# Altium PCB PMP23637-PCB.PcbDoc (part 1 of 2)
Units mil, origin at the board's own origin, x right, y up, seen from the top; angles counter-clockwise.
Board outline 3000 x 2000 mil, 6 copper layers (Top Layer, Layer 2, Signal Layer 3, Signal Layer 4, Layer 5, Bottom Layer), stack 61.712 mil thick; 143 components, 52 nets, 318 pads, 582 vias.
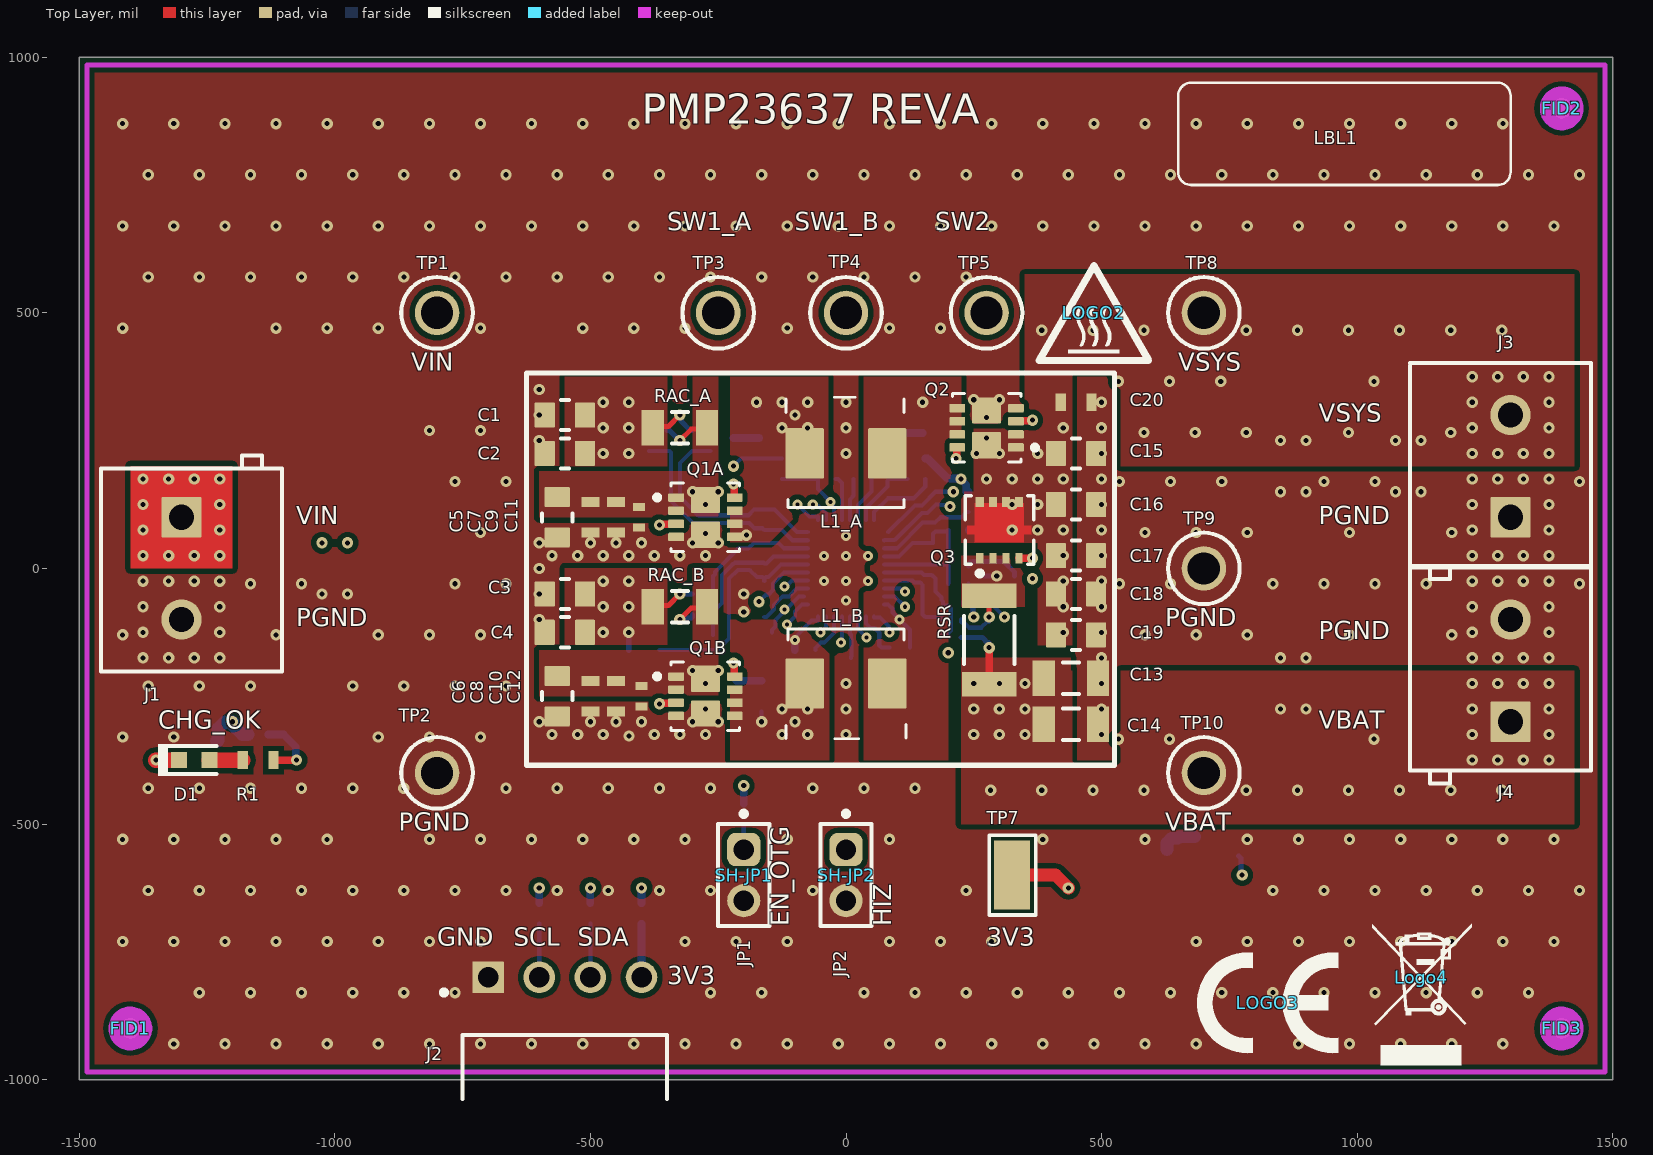
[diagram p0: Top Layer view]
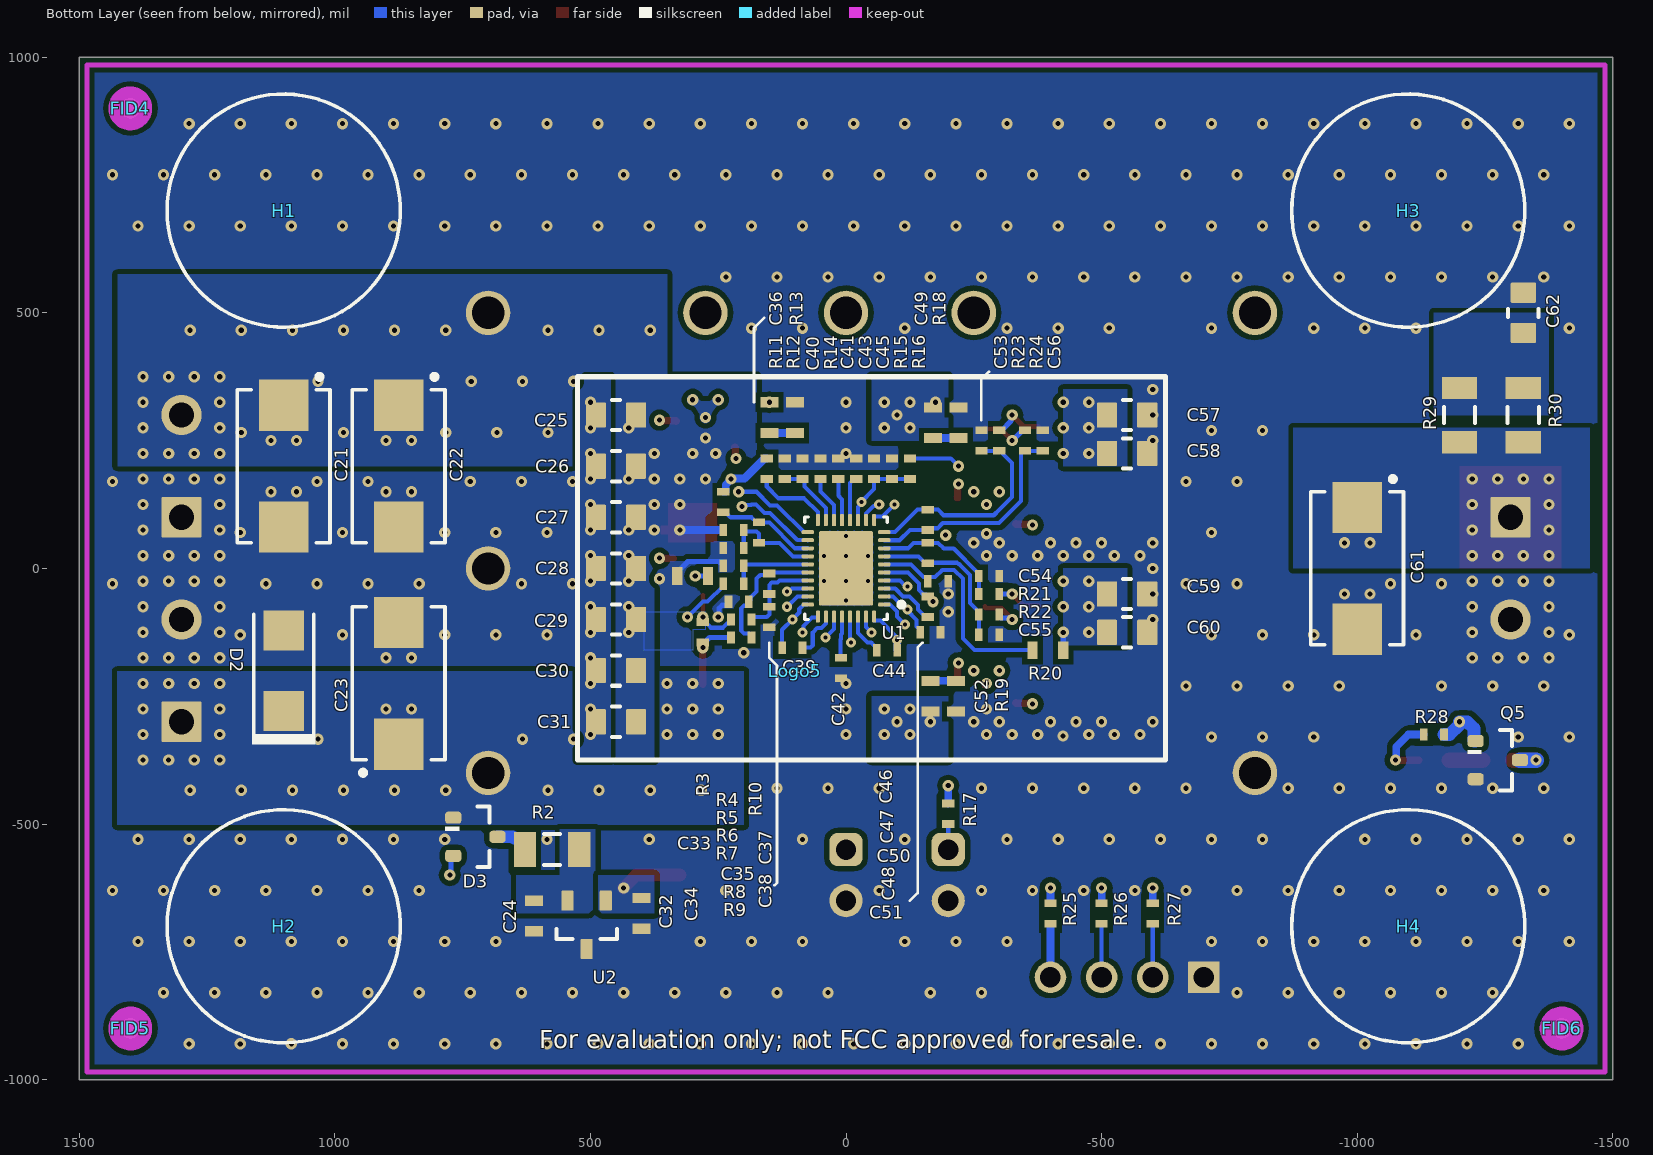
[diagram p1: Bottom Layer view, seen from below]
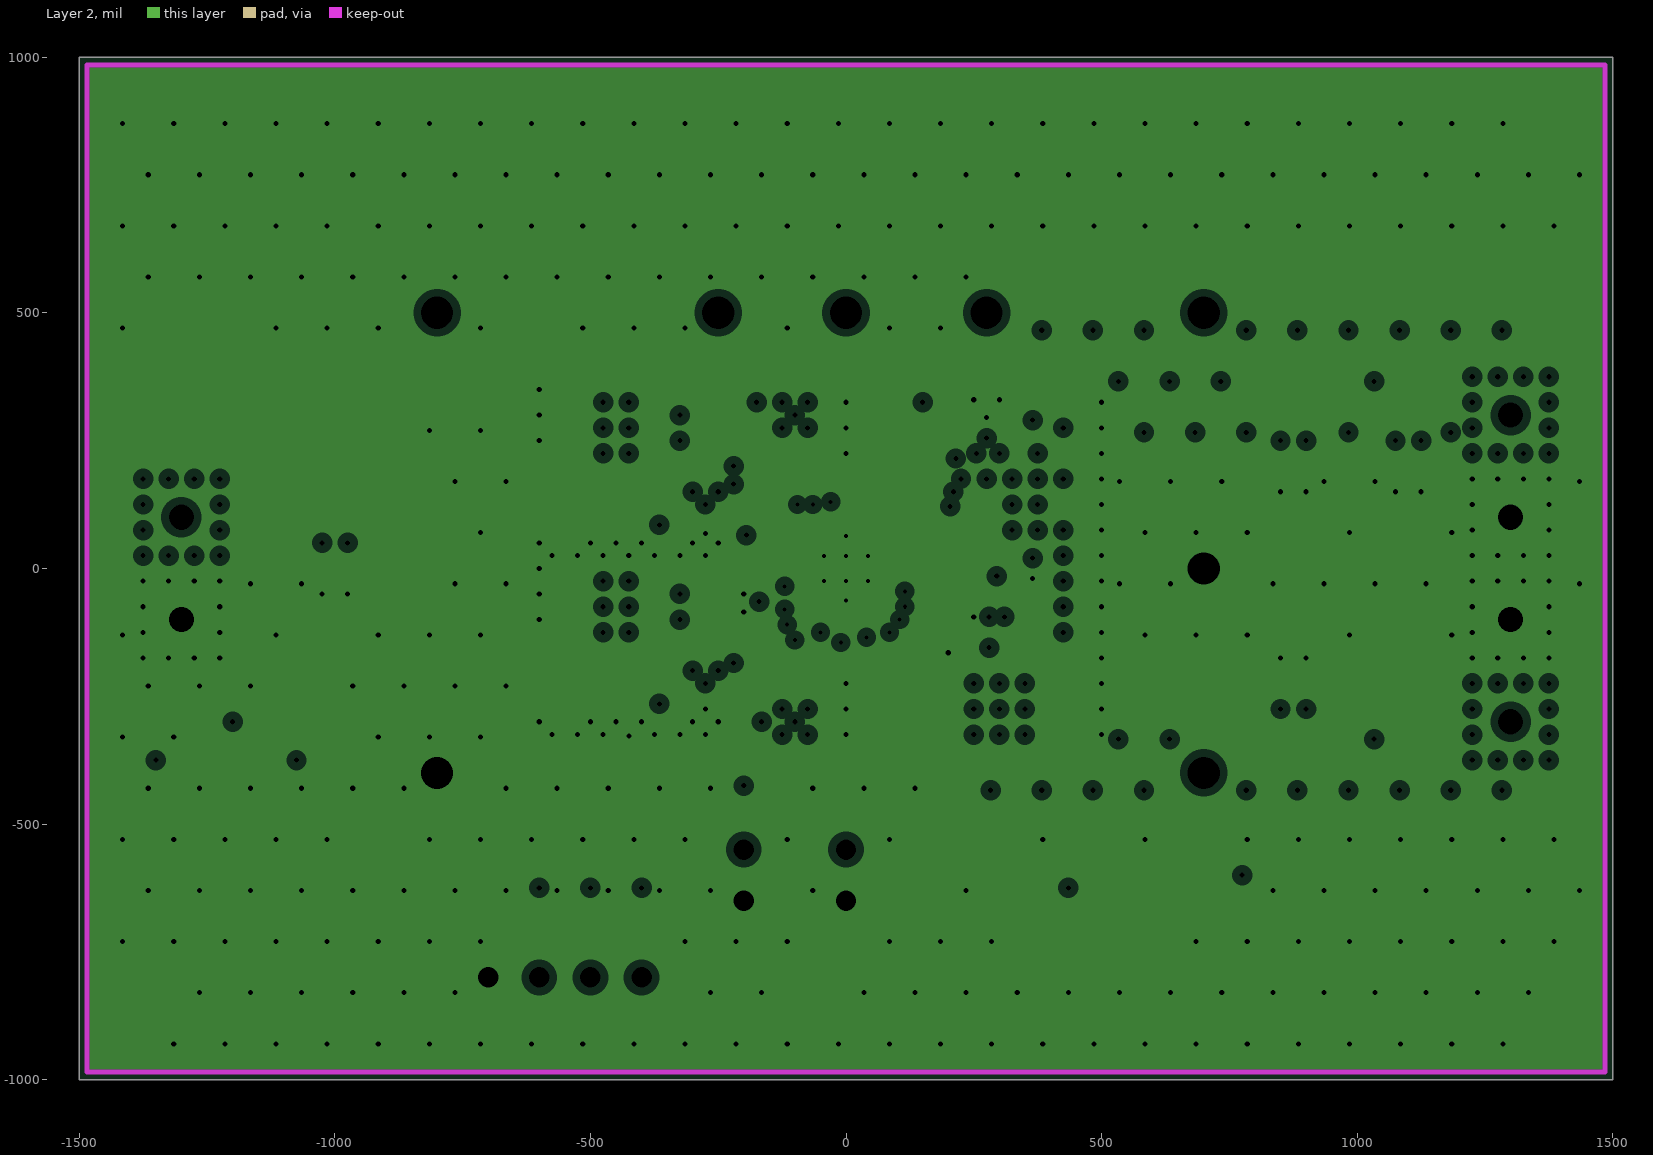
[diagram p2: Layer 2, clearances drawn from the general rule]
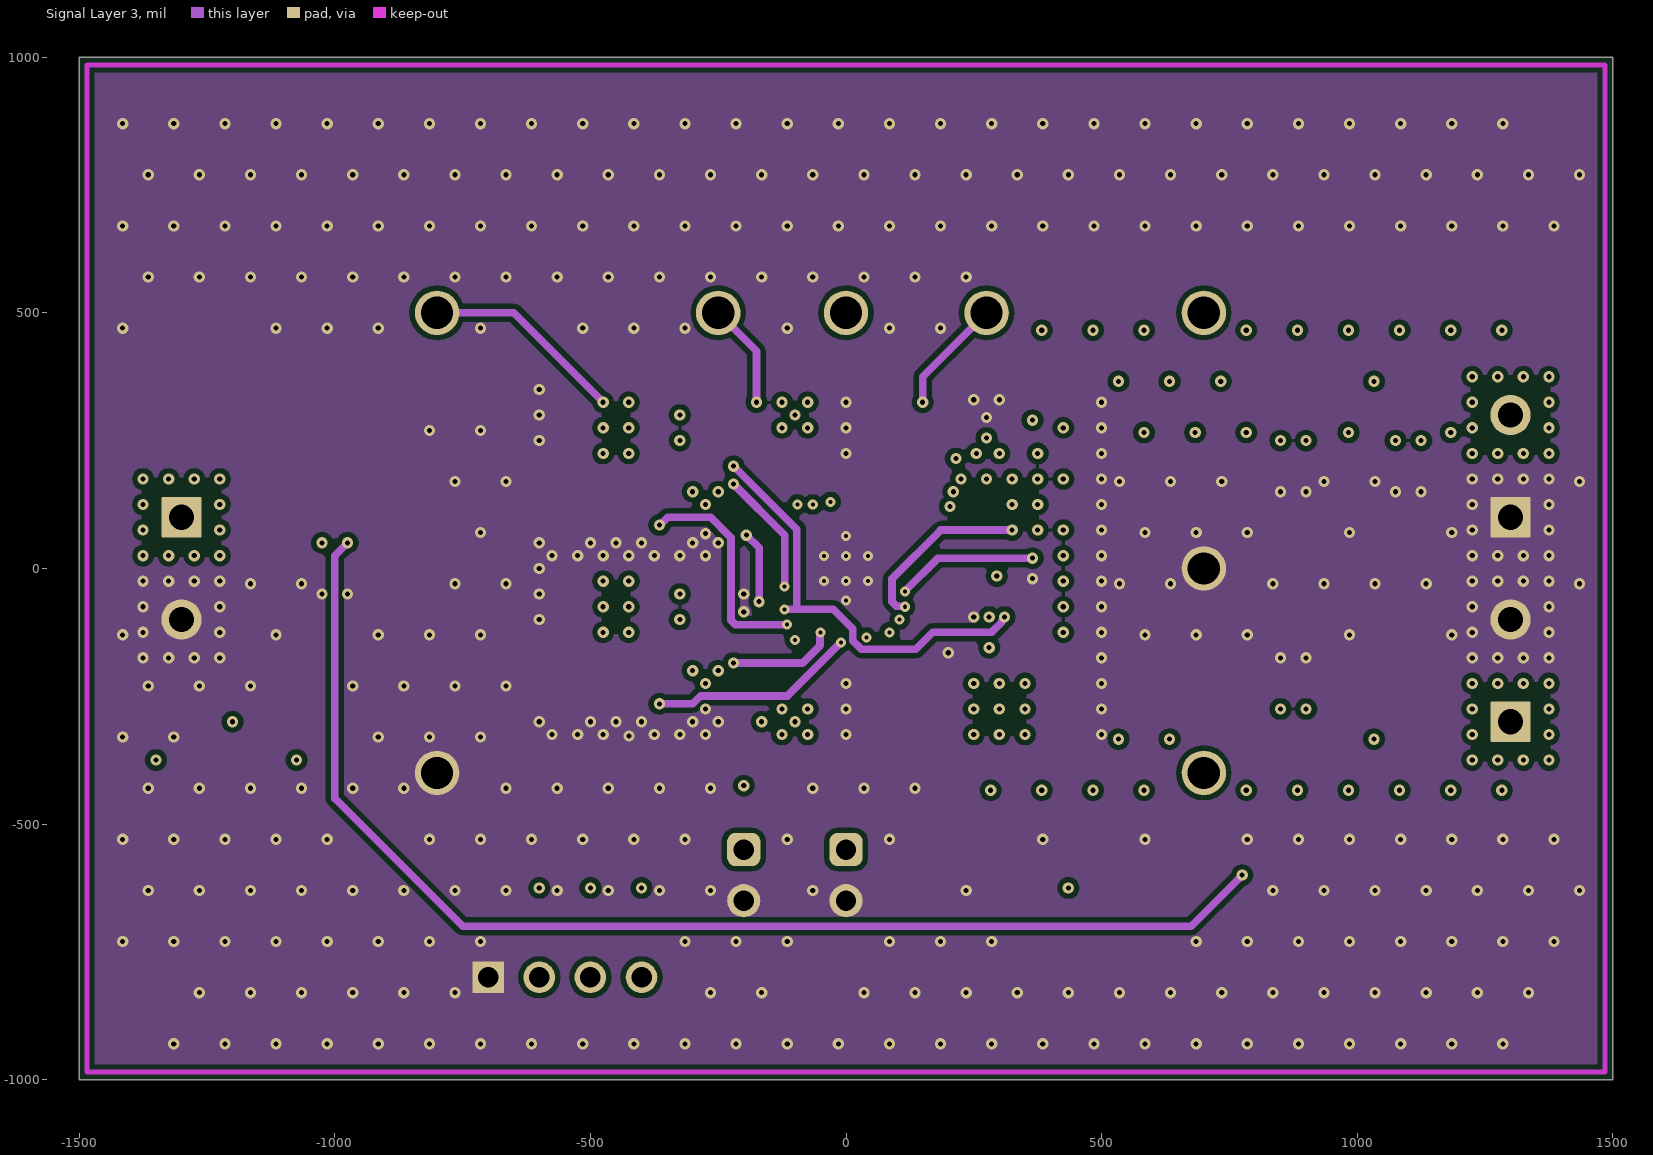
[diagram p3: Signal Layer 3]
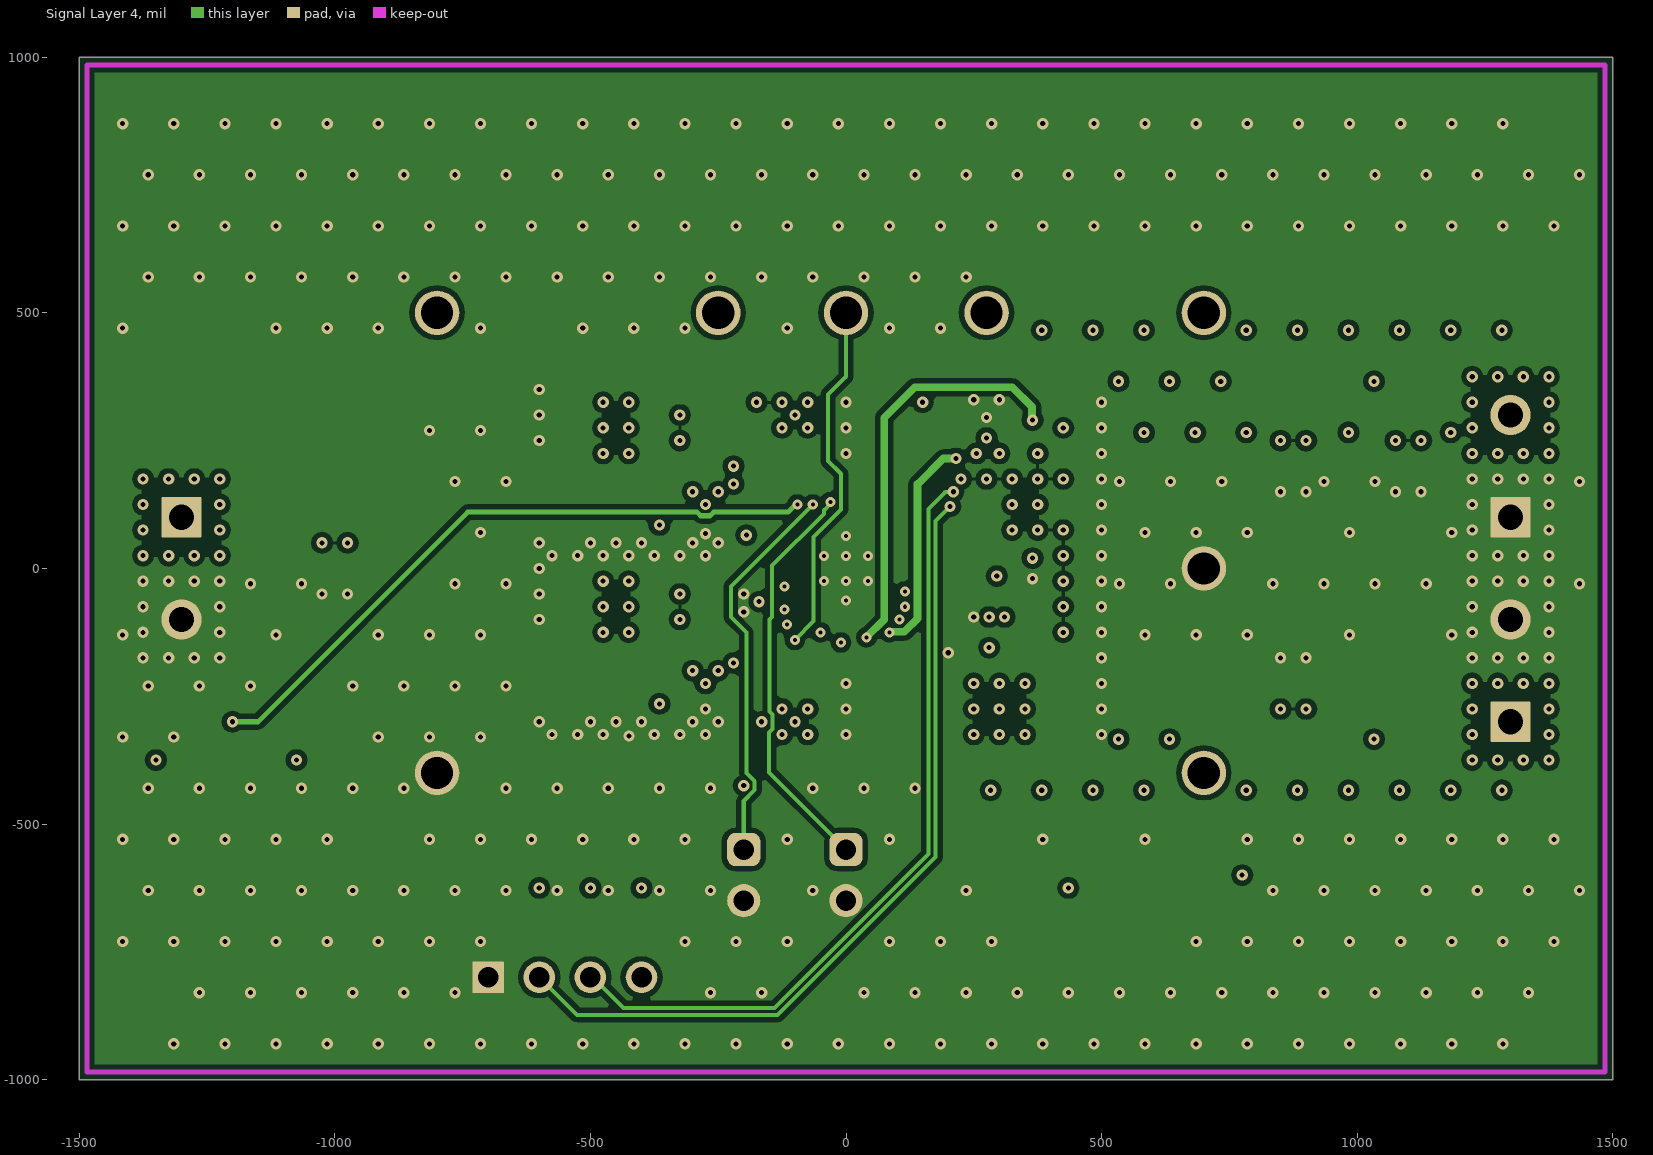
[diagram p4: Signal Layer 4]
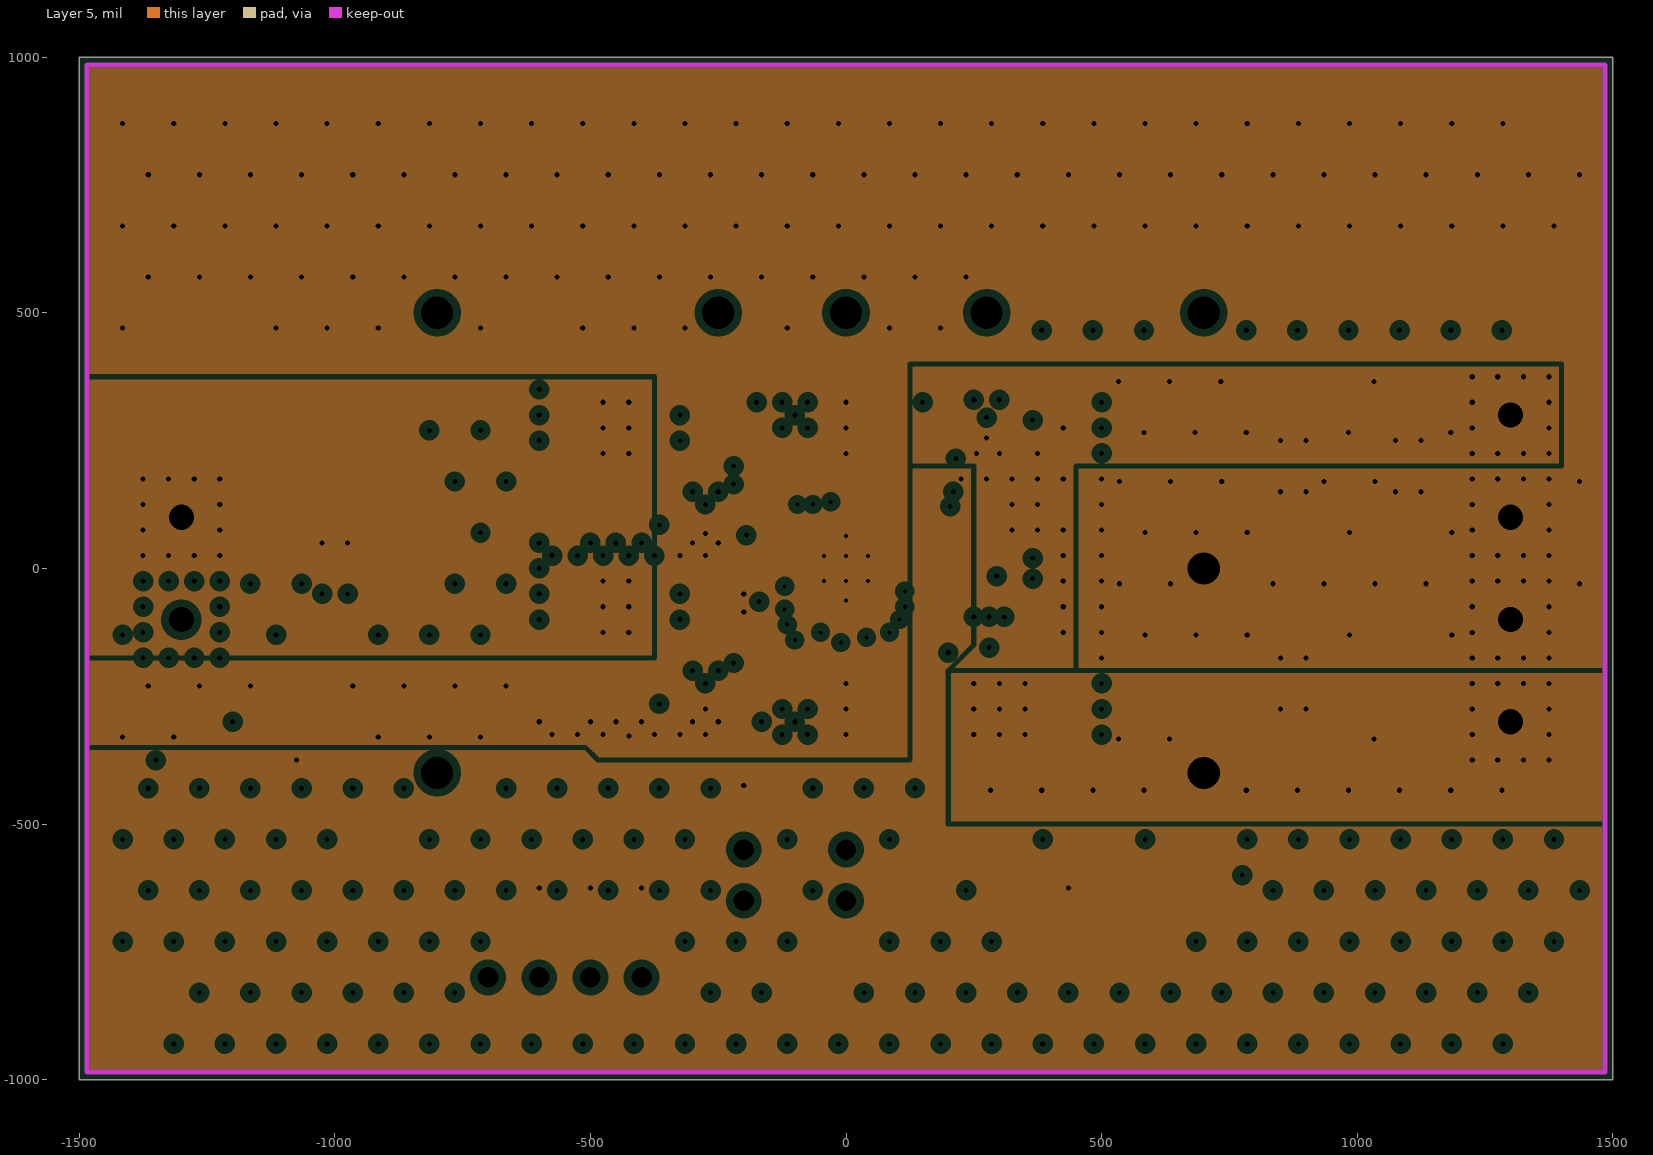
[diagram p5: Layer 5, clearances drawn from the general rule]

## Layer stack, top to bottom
Top Solder: solder mask 0.4, Solder Resist, Dk 3.5
Top Layer: signal copper 2.8
Dielectric1: core 5, FR-4 High TG, Dk 4.2
Layer 2: plane copper 2.756, net PGND
Dielectric 1: prepreg 5, PP-006, Dk 4.1
Signal Layer 3: signal copper 2.8
Dielectric 2: prepreg 25, FR-4 High TG, Dk 4.2
Signal Layer 4: signal copper 2.8
Dielectric 4: prepreg 5, PP-006, Dk 4.1
Layer 5: plane copper 2.756, net (Multiple Nets)
Dielectric 3: core 5, FR-4 High TG, Dk 4.2
Bottom Layer: signal copper 2.8
Bottom Solder: solder mask 0.4, Solder Resist, Dk 3.5

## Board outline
-1500,1000 -1500,-1000 1500,-1000 1500,1000

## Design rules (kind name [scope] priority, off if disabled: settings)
AcuteAngle [All] p1: minimum=4.50000000000000E+0001 checktracksonly=FALSE
AssemblyTestPointUsage [All] p1: valid=2
Clearance "Clearance_gnd polyd" [(InNet('GND') or InNet('PGND')) and inpoly] p1: gap=10 ignorepadtopadclearanceinfootprint=FALSE
Clearance Clearance_FETs [hasfootprint('TRANS_NexFET_Q3') or hasfootprint('TRANS_NexFET_Q3A')] p2: gap=5.9 ignorepadtopadclearanceinfootprint=FALSE except(0: Arc-Hole Track-Hole SMDPad-Hole THPad-Hole Via-Hole Fill-Hole Poly-Hole Region-Hole Text-Hole)
Clearance Clearance_Keepouts [((IsTrack Or IsArc) And Not InPoly) And IsFree and IsKeepOut vs ((IsTrack Or IsArc) And Not InPoly) And IsFree and IsKeepOut] p3: gap=25 ignorepadtopadclearanceinfootprint=FALSE
Clearance Clearance_BoardEdge_MountingHoles [OnCopper and InComponentClass('Mounting Holes') vs IsKeepOut] p4: gap=40 ignorepadtopadclearanceinfootprint=FALSE except(0: Arc-Hole Track-Hole SMDPad-Hole THPad-Hole Via-Hole Fill-Hole Poly-Hole Region-Hole Text-Hole)
Clearance Clearance_BoardEdge_Poly [OnCopper and InPoly vs IsKeepOut] p5: gap=25 ignorepadtopadclearanceinfootprint=FALSE except(0: Arc-Hole Track-Hole SMDPad-Hole THPad-Hole Via-Hole Fill-Hole Poly-Hole Region-Hole Text-Hole)
Clearance Clearance_BoardEdge [OnCopper and Not InComponentClass('Logo') and not InComponentClass('FiducialMark') and not InRegion(1000,500,4000,800) and Not IsKeepout vs IsKeepOut] p6: gap=25 ignorepadtopadclearanceinfootprint=FALSE except(0: Arc-Hole Track-Hole SMDPad-Hole THPad-Hole Via-Hole Fill-Hole Poly-Hole Region-Hole Text-Hole)
Clearance Clearance_Poly [InPolygon] p7: gap=10 ignorepadtopadclearanceinfootprint=FALSE except(0: Arc-Hole Track-Hole SMDPad-Hole THPad-Hole Via-Hole Fill-Hole Poly-Hole Region-Hole Text-Hole)
Clearance [All] p8: gap=6 ignorepadtopadclearanceinfootprint=TRUE
ComponentClearance ComponentClearance_NT [incomponent('NT1') vs incomponent('U1')] p1: gap=0 collisioncheckmode=3 verticalgap=0 showdistances=FALSE
ComponentClearance ComponentClearance_MountingHoles_FiducialMarks [InComponentClass('Mounting Holes') vs InComponentClass('FiducialMark')] p2: gap=50 collisioncheckmode=3 verticalgap=10 showdistances=FALSE
ComponentClearance ComponentClearance_Shunt [InComponentClass('Header') vs InComponentClass('Shunt')] p3: gap=0 collisioncheckmode=3 verticalgap=0 showdistances=FALSE
ComponentClearance ComponentClearance_Logo [InComponentClass('Logo')] p4: gap=50 collisioncheckmode=3 verticalgap=10 showdistances=FALSE
ComponentClearance ComponentClearance_ScrewToNut [(HasFootprint('NY PMS 440 0025 PH')) vs (HasFootprint('Keystone_1902C'))] p5: gap=5 collisioncheckmode=3 verticalgap=10 showdistances=FALSE
ComponentClearance ComponentClearance_MountingHoles [InComponentClass('Mounting Holes')] p6: gap=100 collisioncheckmode=3 verticalgap=100000 showdistances=FALSE
ComponentClearance ComponentClearance_SmallPassives [HasFootprint('0201*') or HasFootprint('0402*') or HasFootprint('0508') or HasFootprint('0603*') or HasFootprint('0612') or HasFootprint('0805*') or HasFootprint('0815*') or HasFootprint('0830*') or HasFootprint('1206*') or HasFootprint('1210*') or HasFootprint('1808*') or HasFootprint('1812*') or HasFootprint('1825*') or HasFootprint('2010*') or HasFootprint('2220*') or HasFootprint('2225*') or HasFootprint('2512*') or HasFootprint('2728*') or HasFootprint('3518*') vs HasFootprint('0201*') or HasFootprint('0402*') or HasFootprint('0508') or HasFootprint('0603*') or HasFootprint('0612') or HasFootprint('0805*') or HasFootprint('0815*') or HasFootprint('0830*') or HasFootprint('1206*') or HasFootprint('1210*') or HasFootprint('1808*') or HasFootprint('1812*') or HasFootprint('1825*') or HasFootprint('2010*') or HasFootprint('2220*') or HasFootprint('2225*') or HasFootprint('2512*') or HasFootprint('2728*') or HasFootprint('3518*')] p7: gap=10 collisioncheckmode=3 verticalgap=10 showdistances=FALSE
ComponentClearance ComponentClearance_THtoSMT [IsThruComponent vs IsSMTComponent] p8: gap=30 collisioncheckmode=3 verticalgap=30 showdistances=FALSE
ComponentClearance ComponentClearance_THtoTH [IsThruComponent vs IsThruComponent] p9: gap=30 collisioncheckmode=3 verticalgap=30 showdistances=FALSE
ComponentClearance [All] p10: gap=20 collisioncheckmode=3 verticalgap=10 showdistances=FALSE
DiffPairsRouting [All] p1: maxlimit=100 minlimit=10 mostfreqgap=10 toplayer_minwidth=10 toplayer_maxwidth=15 toplayer_prefwidth=10 midlayer1_minwidth=10 midlayer1_maxwidth=15 midlayer1_prefwidth=10 midlayer2_minwidth=10 midlayer2_maxwidth=15 midlayer2_prefwidth=10 bottomlayer_minwidth=10 bottomlayer_maxwidth=15 bottomlayer_prefwidth=10 maxuncoupledlength=1000
FabricationTestPointUsage TestPointUsage [All] p1: valid=2 allowmultiple=FALSE
FabricationTestpoint Testpoint [All] p1: side=3 testpointundercomponent=TRUE minsize=40 maxsize=100 preferedsize=60 minholesize=0 maxholesize=40 preferedholesize=32 testpointgrid=1 allowsidetop=TRUE allowsidebottom=TRUE usegrid=TRUE gridtolerance=0.01
FanoutControl Fanout_LCC [IsLCC] p1: bgadir=Out bgaviamode=Centered fanoutstyle=Auto fanoutdirection=Alternating viagrid=1 // Fanout_LCC (Default Rule)
FanoutControl Fanout_BGA [IsBGA] p2: bgadir=Out bgaviamode=Centered fanoutstyle=Auto fanoutdirection=Alternating viagrid=1 // Fanout_BGA (Default Rule)
FanoutControl Fanout_Default [All] p4: bgadir=Out bgaviamode=Centered fanoutstyle=Auto fanoutdirection=Alternating viagrid=1 // Fanout_Default (Default Rule)
FanoutControl Fanout_Small [(CompPinCount < 5)] p5: bgadir=Out bgaviamode=Centered fanoutstyle=Auto fanoutdirection=OutThenIn viagrid=1 // Fanout_Small (Default Rule)
HoleSize [All] p1: absolutevalues=TRUE maxlimit=251 minlimit=7.8 maxpercent=80.000 minpercent=20.000
MinimumAnnularRing MinimumAnnularRing_ThermalPadVias [IsVia and InAnyComponent] p1: minimumring=5
MinimumAnnularRing [All] p2: minimumring=5
MinimumSolderMaskSliver MinimumSolderMaskSliver_Logo [InComponentClass('Logo') vs InComponentClass('Logo')] p1: minsoldermaskwidth=0.7
MinimumSolderMaskSliver [All] p2: minsoldermaskwidth=3.94
PlaneClearance [All] p1: clearance=15
PlaneConnect [All] p1: planeconnectstyle=Direct reliefexpansion=10 reliefentries=4 reliefconductorwidth=10 reliefairgap=10
PolygonConnect [All] p1: connectstyle=Direct reliefconductorwidth=10 reliefentries=4 polygonreliefangle="90 Angle" airgapwidth=10
RoutingVias ThermalPadVias [IsVia and InAnyComponent] p1: holewidth=7.87 width=19.68 viastyle="Through Hole" minholewidth=7.87 minwidth=19.68 maxholewidth=12.99 maxwidth=23.62
RoutingVias [All] p2: holewidth=10 width=22 viastyle="Through Hole" minholewidth=7.87 minwidth=18 maxholewidth=40 maxwidth=65
SilkToBoardRegionClearance [Not ((IsComment or IsDesignator) And (Hide <> 'False')) and not InRegion(1000,500,4000,800)] p1:
SilkToSilkClearance SilkToSilkClearance_Pb-FreeLogo [(HasFootprint('Pb-Free_Overlay_Medium') OR HasFootprint('Pb-Free_Overlay_Small')) vs (HasFootprint('Pb-Free_Overlay_Medium') OR HasFootprint('Pb-Free_Overlay_Small'))] p1: silktosilkclearance=0
SilkToSilkClearance [All] p2: silktosilkclearance=3
SilkToSolderMaskClearance "SilkToSolderMaskClearance FETS" [all vs hasfootprint('TRANS_NexFET_Q3A')] p1: minsilkscreentomaskgap=0.5 clearancetoexposedcopper=FALSE
SilkToSolderMaskClearance "Silk to Solder Mask Opening" [All] p2: minsilkscreentomaskgap=3 clearancetoexposedcopper=FALSE
SolderMaskExpansion [All] p1: expansion=1.97 istentingtop=FALSE
SupplyNets "Schematic Supply Nets_6" [InNet('PGND')] p1: voltage=0.000
SupplyNets "Schematic Supply Nets_5" [InNet('VIN')] p2: voltage=0.000
SupplyNets "Schematic Supply Nets_4" [InNet('3V3')] p3: voltage=0.000
SupplyNets "Schematic Supply Nets_1" [InNet('VSYS')] p4: voltage=0.000
SupplyNets "Schematic Supply Nets" [InNet('VBAT')] p5: voltage=0.000
Width [All] p1: maxlimit=100 minlimit=8 preferedwidth=10
14 further rules are at their usual default settings.

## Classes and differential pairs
component class BMS059A_Hardware: C24 C32 D3 FID1 FID2 FID3 FID4 FID5 FID6 H1 H2 H3 H4 LBL1 LOGO2 LOGO3 Logo4 Logo5 R2 SH-JP1 SH-JP2 TP7 U2 ZZ1 ZZ2 ZZ3 ZZ4
component class FiducialMark: FID1 FID2 FID3 FID4 FID5 FID6
component class AssemblyNote: ZZ1 ZZ2 ZZ3 ZZ4
component class Label: LBL1
component class BMS059A: C1 C2 C3 C4 C5 C6 C7 C8 C9 C10 C11 C12 C13 C14 C15 C16 C17 C18 C19 C20 C21 C22 C23 C25 C26 C27 C28 C29 C30 C31 C33 C34 C35 C36 C37 C38 C39 C40 C41 C42 C43 C44 C45 C46 C47 C48 C49 C50 C51 C52 C53 C54 C55 C56 C57 C58 C59 C60 C61 C62 D1 D2 J1 J2 J3 J4 JP1 JP2 L1_A L1_B Q1A Q1B Q2 Q3 Q5 Q12 Q13 R1 R3 R4 R5 R6 R7 R8 R9 R10 R11 R12 R13 R14 R15 R16 R17 R18 R19 R20 R21 R22 R23 R24 R25 R26 R27 R28 R29 R30 RAC_A RAC_B RSR TP1 TP2 TP3 TP4 TP5 TP8 TP9 TP10 U1
component class Header: JP1 JP2
component class Shunt: SH-JP1 SH-JP2

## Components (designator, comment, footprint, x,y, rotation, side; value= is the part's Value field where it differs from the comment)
C1 "C2012JB1V106K125AC" 0805_HV1 -550,300 r180 top value=10uF (schematic designator C17)
C2 "C2012JB1V106K125AC" 0805_HV1 -550,225 r180 top value=10uF (schematic designator C16)
C3 "C2012JB1V106K125AC" 0805_HV1 -550,-50 r180 top value=10uF (schematic designator C4)
C4 "C2012JB1V106K125AC" 0805_HV1 -550,-125 r180 top value=10uF (schematic designator C3)
C5 "C2012JB1V106K125AC" 0805_HV1 -565,100 r270 top value=10uF (schematic designator C20)
C6 "C2012JB1V106K125AC" 0805_HV1 -565,-250 r270 top value=10uF (schematic designator C7)
C7 "C1608X5R1H105K080AB" 0603S -500,100 r270 top value=1uF (schematic designator C19)
C8 "C1608X5R1H105K080AB" 0603S -500,-250 r270 top value=1uF (schematic designator C6)
C9 "C0603C103J5RACTU" 0603S -450,100 r270 top value=0.01uF (schematic designator C21)
C10 "C0603C103J5RACTU" 0603S -450,-250 r270 top value=0.01uF (schematic designator C8)
C11 "04025C102JAT2A" 0402S -405,100 r270 top value=1000pF (schematic designator C22)
C12 "04025C102JAT2A" 0402S -400,-250 r270 top value=1000pF (schematic designator C9)
C13 "GMK316AB7106KL-TR" 1206_190L 440,-215 r0 top value=10uF (schematic designator C39)
C14 "GMK316AB7106KL-TR" 1206_190L 440,-305 r0 top value=10uF (schematic designator C34)
C15 "C2012JB1V106K125AC" 0805_HV1 450,225 r0 top value=10uF (schematic designator C10)
C16 "C2012JB1V106K125AC" 0805_HV1 450,125 r0 top value=10uF (schematic designator C11)
C17 "C2012JB1V106K125AC" 0805_HV1 450,25 r0 top value=10uF (schematic designator C12)
C18 "C2012JB1V106K125AC" 0805_HV1 450,-50 r0 top value=10uF (schematic designator C13)
C19 "C2012JB1V106K125AC" 0805_HV1 450,-130 r0 top value=10uF (schematic designator C14)
C20 "C0603C103J5RACTU" 0603S 450,325 r0 top value=0.01uF (schematic designator C15)
C21 "T521X336M050ATE050" 7343-43 1100,200 r270 bottom value=33uF (schematic designator C24)
C22 "T521X336M050ATE050" 7343-43 875,200 r270 bottom value=33uF (schematic designator C23)
C23 "T521X336M050ATE050" 7343-43 875,-225 r90 bottom value=33uF (schematic designator C35)
C24 "C1608X5R1H105K080AB" 0603S 610,-680 r90 bottom value=1uF (schematic designator C77)
C25 "C2012JB1V106K125AC" 0805_HV1 450,300 r0 bottom value=10uF (schematic designator C32)
C26 "C2012JB1V106K125AC" 0805_HV1 450,200 r0 bottom value=10uF (schematic designator C18)
C27 "C2012JB1V106K125AC" 0805_HV1 450,100 r0 bottom value=10uF (schematic designator C5)
C28 "C2012JB1V106K125AC" 0805_HV1 450,0 r0 bottom value=10uF (schematic designator C49)
C29 "C2012JB1V106K125AC" 0805_HV1 450,-100 r0 bottom value=10uF (schematic designator C56)
C30 "C2012JB1V106K125AC" 0805_HV1 450,-200 r0 bottom value=10uF (schematic designator C45)
C31 "C2012JB1V106K125AC" 0805_HV1 450,-300 r0 bottom value=10uF (schematic designator C41)
C32 "GRM188R6YA106MA73D" 0603S 400,-675 r90 bottom value=10uF (schematic designator C76)
C33 "C1608X5R1H105K080AB" 0603S 300,-15 r0 bottom value=1uF (schematic designator C30)
C34 "GRM155R71H104ME14D" 0402S 280,-125 r270 bottom value=0.1uF (schematic designator C33)
C35 "GRM155R71H223KA12D" 0402S 210,-65 r0 bottom value=0.022uF (schematic designator C69)
C36 "Capacitor" 0603S 150,295 r270 bottom value=330pF (schematic designator C46)
C37 "CGA2B3X7R1H683K050BB" 0402S 150,-30 r90 bottom value=0.068uF (schematic designator C68)
C38 "GRM155R71H223KA12D" 0402S 150,-95 r270 bottom value=0.022uF (schematic designator C67)
C39 "CGA2B3X7R1E104K050BB" 0402S 105,-155 r0 bottom value=0.1uF (schematic designator C27)
C40 "GRM1555C1H101JA01D" 0402S 85,195 r90 bottom value=100pF (schematic designator C44)
C41 "GRM1555C1H101JA01D" 0402S 15,195 r90 bottom value=100pF (schematic designator C38)
C42 "GRM155R61E225ME15D" 0402S 10,-195 r90 bottom value=2.2uF (schematic designator C26)
C43 "GRM1555C1H101JA01D" 0402S -20,195 r90 bottom value=100pF (schematic designator C37)
C44 "CGA2B3X7R1E104K050BB" 0402S -80,-160 r180 bottom value=0.1uF (schematic designator C25)
C45 "GRM1555C1H101JA01D" 0402S -55,195 r90 bottom value=100pF (schematic designator C36)
C46 "C1005X7R1H104K050BE" 0402S -160,95 r270 bottom value=0.1uF (schematic designator C29)
C47 "C1005X7R1H104K050BE" 0402S -160,30 r270 bottom value=0.1uF (schematic designator C2)
C48 "CGA2B3X7R1E104K050BB" 0402S -160,-75 r90 bottom value=0.1uF (schematic designator C31)
C49 "Capacitor" 0603S -170,285 r270 bottom value=330pF (schematic designator C54)
C50 "GRM155R61E474KE01D" 0402S -180,-25 r180 bottom value=0.47uF (schematic designator C70)
C51 "GRM155R61E225ME15D" 0402S -165,-125 r180 bottom value=2.2uF (schematic designator C28)
C52 "Capacitor" 0603S -165,-250 r90 bottom value=330pF (schematic designator C40)
C53 "CGA2B3X7R1H333K050BB" 0402S -265,250 r90 bottom value=0.033uF (schematic designator C74)
C54 "CGA2B3X7R1H333K050BB" 0402S -280,-15 r180 bottom value=0.033uF (schematic designator C73)
C55 "CGA2B3X7R1H333K050BB" 0402S -280,-130 r180 bottom value=0.033uF (schematic designator C72)
C56 "CGA2B3X7R1H333K050BB" 0402S -385,250 r90 bottom value=0.033uF (schematic designator C75)
C57 "C2012JB1V106K125AC" 0805_HV1 -550,300 r180 bottom value=10uF (schematic designator C43)
C58 "C2012JB1V106K125AC" 0805_HV1 -550,225 r180 bottom value=10uF (schematic designator C42)
C59 "C2012JB1V106K125AC" 0805_HV1 -550,-50 r180 bottom value=10uF (schematic designator C47)
C60 "C2012JB1V106K125AC" 0805_HV1 -550,-125 r180 bottom value=10uF (schematic designator C55)
C61 "T521X336M050ATE050" 7343-43 -1000,0 r270 bottom value=33uF (schematic designator C1)
C62 "GCM21BR71H105KA03K" 0805_HV1 -1325,500 r90 bottom value=1uF (schematic designator C48)
D1 "LED" LED_LTST-C190 -1275,-375 r180 top value=Green
D2 "B240A-13-F" SMA 1100,-200 r90 bottom value=40V
D3 "BAV70-E3-08" SOT-23L 725,-525 r180 bottom value=70V
FID1 "Fiducial" Fiducial10-20 -1400,-900 r0 top (schematic designator FID2)
FID2 "Fiducial" Fiducial10-20 1400,900 r0 top (schematic designator FID1)
FID3 "Fiducial" Fiducial10-20 1400,-900 r0 top
FID4 "Fiducial" Fiducial10-20 1400,900 r90 bottom
FID5 "Fiducial" Fiducial10-20 1400,-900 r90 bottom
FID6 "Fiducial" Fiducial10-20 -1400,-900 r90 bottom
H1 "Bumpon" Bumpon_SJ5003Transparent 1100,700 r180 bottom
H2 "Bumpon" Bumpon_SJ5003Transparent 1100,-700 r180 bottom (schematic designator H3)
H3 "Bumpon" Bumpon_SJ5003Transparent -1100,700 r180 bottom (schematic designator H2)
H4 "Bumpon" Bumpon_SJ5003Transparent -1100,-700 r180 bottom
J1 "Receptacle_2x1" On-Shore_ED120_2DS -1300,0 r270 top
J2 "0022053041" FP-22-05-3041_HDR4-MFG -550,-1078.44 r0 top (schematic designator J8)
J3 "ED120/2DS" On-Shore_ED120_2DS 1300,200 r90 top (schematic designator J2)
J4 "ED120/2DS" On-Shore_ED120_2DS 1300,-200 r90 top (schematic designator J3)
JP1 "TSW-102-07-G-S" TSW-102-07-G-S -200,-600 r270 top (schematic designator JP2)
JP2 "TSW-102-07-G-S" TSW-102-07-G-S 0,-600 r270 top (schematic designator JP3)
L1_A "CMLB051H-2R2MS" FP-CMLB051H-2R2MS_SMT25MM4_5MM2-MFG 0,225 r0 top value=2.2uH
L1_B "CMLB051H-2R2MS" FP-CMLB051H-2R2MS_SMT25MM4_5MM2-MFG 0,-225 r0 top value=2.2uH
LBL1 "THT-14-423-10" Label_650x200 975,850 r0 top
LOGO2 "CAUTION HOT SURFACE" IEC_HotSurface_Small 485,500 r0 top (schematic designator LOGO3)
LOGO3 "CE Mark" CE_Mark_5mm 825,-850 r0 top (schematic designator LOGO5)
Logo4 "WEEE logo" WEEE_Minimum 1125,-800 r0 top
Logo5 "FCC disclaimer" FCC_disclaimer 100,-200 r180 bottom (schematic designator Logo1)
Q1A "AONP36336" FP-AONP36336_DFN3.3x3.3B-MFG -275,100 r0 top
Q1B "AONP36336" FP-AONP36336_DFN3.3x3.3B-MFG -275,-250 r0 top
Q2 "AONP36336" FP-AONP36336_DFN3.3x3.3B-MFG 275,275 r180 top
Q3 "AON7534" TRANS_AOS_DFN3X3 300,75 r90 top value=30V
Q5 "MOSFET_N_D3G1S2" SOT-23L -1275,-375 r180 bottom value=60V (schematic designator Q7)
R1 "Resistor" 0603S -1150,-375 r0 top value=2.00k (schematic designator R19)
R2 "ERJ-8ENF10R0V" 1206L 575,-550 r0 bottom value=10.0 (schematic designator R47)
R3 "CRCW040210K0FKED" 0402S 240,130 r90 bottom value=10.0k (schematic designator R11)
R4 "CRCW040210K0FKED" 0402S 220,75 r180 bottom value=10.0k (schematic designator R38)
R5 "CRCW0402300KFKED" 0402S 220,40 r180 bottom value=300k (schematic designator R42)
R6 "RC0402FR-07100KL" 0402S 220,5 r180 bottom value=100k (schematic designator R20)
R7 "RC0402FR-0733KL" 0402S 220,-30 r0 bottom value=33.0k (schematic designator R23)
R8 "CRCW040210R0JNED" 0402S 205,-100 r0 bottom value=10 (schematic designator R9)
R9 "CRCW040210R0JNED" 0402S 205,-135 r0 bottom value=10 (schematic designator R10)
R10 "CRCW04022M00JNED" 0402S 170,70 r270 bottom value=2.0Meg (schematic designator R39)
R11 "CRCW040210K0FKED" 0402S 155,195 r270 bottom value=10.0k (schematic designator R14)
R12 "CRCW040215K0FKED" 0402S 120,195 r90 bottom value=15.0k (schematic designator R17)
R13 "Resistor" 0603S 100,295 r270 bottom value=56 (schematic designator R26)
R14 "CRCW04023K57FKED" 0402S 50,195 r270 bottom value=3.57k (schematic designator R18)
R15 "CRCW0402300KFKED" 0402S -90,195 r90 bottom value=300k (schematic designator R16)
R16 "CRCW0402200KFKED" 0402S -125,195 r270 bottom value=200k (schematic designator R15)
R17 "CRCW040210K0FKED" 0402S -200,-480 r90 bottom value=10.0k (schematic designator R44)
R18 "Resistor" 0603S -220,285 r270 bottom value=56 (schematic designator R27)
R19 "Resistor" 0603S -215,-250 r90 bottom value=56 (schematic designator R25)
R20 "CRCW06031R00JNEA" 0603S -395,-160 r180 bottom value=1.0 (schematic designator R32)
R21 "Resistor" 0402S -280,-50 r180 bottom value=4.99 (schematic designator R1)
R22 "Resistor" 0402S -280,-90 r180 bottom value=4.99 (schematic designator R2)
R23 "Resistor" 0402S -300,250 r90 bottom value=4.99 (schematic designator R6)
R24 "Resistor" 0402S -350,250 r90 bottom value=4.99 (schematic designator R7)
R25 "CRCW0402100RJNED" 0402S -400,-675 r270 bottom value=100 (schematic designator R46)
R26 "CRCW040210K0FKED" 0402S -500,-675 r90 bottom value=10.0k (schematic designator R13)
R27 "CRCW040210K0FKED" 0402S -600,-675 r90 bottom value=10.0k (schematic designator R12)
R28 "Resistor" 0402S -1150,-325 r180 bottom value=10.0k (schematic designator R43)
R29 "Resistor" 1206L -1200,300 r270 bottom value=3.9 (schematic designator R28)
R30 "Resistor" 1206L -1325,300 r270 bottom value=3.9 (schematic designator R29)
RAC_A "WSLP1206R0100FEA" 1206L -325,275 r0 top value=0.01
RAC_B "WSLP1206R0100FEA" 1206L -325,-75 r0 top value=0.01
RSR "CSNL2010FT5L00" 2010L 280,-140 r270 top value=0.005
SH-JP1 "SNT-100-BK-G" SNT-100-BK-G -200,-600 r90 top value=1x2 (schematic designator SH-JP2)
SH-JP2 "SNT-100-BK-G" SNT-100-BK-G 0,-600 r90 top value=1x2 (schematic designator SH-JP3)
TP1 "5010" Keystone5010 -800,500 r0 top (schematic designator TP20)
TP2 "5011" Keystone5011 -800,-400 r0 top (schematic designator TP21)
TP3 "5012" Keystone5012 -250,500 r90 top (schematic designator TP15)
TP4 "5012" Keystone5012 0,500 r270 top (schematic designator TP16)
TP5 "5012" Keystone5012 275,500 r90 top (schematic designator TP17)
TP7 "5015" Testpoint_Keystone_Miniature 325,-600 r90 top (schematic designator TP60)
TP8 "5010" Keystone5010 700,500 r0 top (schematic designator TP22)
TP9 "5011" Keystone5011 700,0 r0 top (schematic designator TP19)
TP10 "5010" Keystone5010 700,-400 r0 top
U1 "BQ25770REER" REE0036A-MFG 0,0 r0 bottom
U2 "LM3480IM3-3.3/NOPB" DBZ0003A_N 507.4,-697.24 r270 bottom
ZZ1 "This Assembly Note is for PCB labels only" AssemblyNoteLabel -1680,2490 r0 top
ZZ2 "These assemblies are ESD sensitive, ESD precautions shall be observed." AssemblyNote -1680,2390 r0 top
ZZ3 "These assemblies must be clean and free from flux and all contaminants. Use of no clean flux is not acceptable." AssemblyNote -1680,2290 r0 top
ZZ4 "These assemblies must comply with workmanship standards IPC-A-610 Class 2, unless otherwise specified." AssemblyNote -1680,2190 r0 top

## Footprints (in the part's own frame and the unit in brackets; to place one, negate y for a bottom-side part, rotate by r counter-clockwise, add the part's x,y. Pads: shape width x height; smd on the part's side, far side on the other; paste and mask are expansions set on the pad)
0402S [mil] "Based on C0402S footprint from PADS legacy"
  rect 15x24 smd: 1(-20,0) 2(20,0)
  body extent -22,-12 22,12, height 24
0603S [mil]
  rect 20x35 smd: 1(-30,0) 2(30,0)
  body extent -34,-19 34,19, height 39
0805_HV1 [mm] "Custom footprint based on analyzing multiple manufacturer recommendations"
  rrect10% 1x1.25 smd: 1(-1,0) 2(1,0)
  silkscreen extent -0.2,-0.75 0.2,0.75, body extent -1.1,-0.72 1.1,0.73, height 1.45
1206_190L [mm] "1206_190"
  rect 1.1x1.75 smd: 1(-1.35,0) 2(1.35,0)
  silkscreen extent -0.4,-0.77 0.4,0.77, body extent -1.75,-0.95 1.75,0.95, height 1.9
1206L [mm] "1206 from SM-752 data"
  rect 1.1x1.75 smd: 1(-1.35,0) 2(1.35,0)
  silkscreen extent -0.4,-0.77 0.4,0.77, body extent -1.7,-0.9 1.7,0.9, height 1.35
2010L [mm]
  rect 1.2x2.7 smd: 1(-2.2,0) 2(2.2,0)
  silkscreen extent -1.2,-1.25 1.2,1.25, body extent -2.73,-1.45 2.73,1.45, height 1.66
7343-43 [mm] "Medium density IPC based on Kemet T495 series"
  rect 2.55x2.45 smd: 1(-3.025,0) 2(3.025,0)
  silkscreen extent -4.56,-2.3 3.8,2.3, body extent -3.8,-2.3 3.8,2.3, height 4.3
AssemblyNote [mil] "Assembly Note"
AssemblyNoteLabel [mil] "Assembly Note for PCB Labels"
Bumpon_SJ5003Transparent [mil] "3M Hemispherical Bumpon transparent"
  round 1 on Mech4: 0(0,0)
  silkscreen extent -228,-228 228,228, body extent -219,-219 219,219, height 197
CE_Mark_5mm [mil] "Minimum text height for CE Mark"
  silkscreen extent -138,-98 138,98
DBZ0003A_N [mm] "SOT23, 3-Leads, Body 2.9x1.3mm, Pitch 0.95mm, Lead Span 2.4mm, IPC Medium Density"
  rrect17% 1x0.6 smd: 1(-1.2,0.95) 2(-1.2,-0.95) 3(1.2,0)
  silkscreen extent 0.2,-1.5 0.7,1.5, body extent -1.26,-1.46 1.26,1.46, height 0.98
FCC_disclaimer [mil]
Fiducial10-20 [mm]
  round 1 smd mask+0.5: 1(0,0)
  Top Layer keep-out circle w1.178: c0,0 r0.5
FP-22-05-3041_HDR4-MFG [mm]
  rrect6% 1.57x1.57 hole 1.02 paste-2539.97 mask+0: 1(-3.81,7.073)
  round 1.57 hole 1.02 paste-2539.97 mask+0: 2(-1.27,7.073) 3(1.27,7.073) 4(3.81,7.073)
  silkscreen extent -6.13,1.03 5.08,6.44, body extent -5.18,-6.28 5.18,7.96, height 0.25
FP-AONP36336_DFN3.3x3.3B-MFG [mm]
  rrect24% 0.79x0.42 smd paste+0 mask+0: 1(-1.455,0.975) 2(-1.455,0.325) 3(-1.455,-0.325) 4(-1.455,-0.975) 5(1.455,-0.975) 6(1.455,-0.325) 7(1.455,0.325) 8(1.455,0.975)
  rrect8% 1.44x1.3 smd paste+0 mask+0: 9(0,0.865) 10(0,-0.865)
  silkscreen extent -2.52,-1.7 1.7,1.7, body extent -1.95,-1.8 1.95,1.8, height 0.25
FP-CMLB051H-2R2MS_SMT25MM4_5MM2-MFG [mm]
  rrect5% 1.895x2.5 smd paste+0 mask+0: 1(-2.047,0) 2(2.047,0)
  silkscreen extent -2.97,-2.7 2.88,2.7, body extent -3.1,-2.8 3.1,2.8, height 0.25
IEC_HotSurface_Small [mil]
  silkscreen extent -107,-93 107,92
Keystone5010 [mil] "Keystone Multipurpose loops"
  round 87 hole 63: 1(0,0)
  silkscreen extent -70,-70 70,70, body extent -63,-63 63,62, height 319
Keystone5011 [mil] "Keystone Multipurpose loops"
  round 87 hole 63: 1(0,0)
  silkscreen extent -70,-70 70,70, body extent -63,-63 63,62, height 319
Keystone5012 [mil] "Keystone Multipurpose loops"
  round 87 hole 63: 1(0,0)
  silkscreen extent -70,-70 70,70, body extent -63,-63 63,62, height 319
Label_650x200 [mil] "Thermal Transfer Label"
  round 1 on Mech13: 0(0,0)
  silkscreen extent -325,-100 325,100, body extent -325,-100 325,100, height 1
LED_LTST-C190 [mm] "Lite-On"
  rect 0.8x0.8 smd: 1(-0.75,0) 2(0.75,0)
  silkscreen extent -1.1,-0.8 1.8,0.8, body extent -0.85,-0.45 0.85,0.45, height 0.9
On-Shore_ED120_2DS [mm] "ONSHORE"
  rrect5% 2x2 hole 1.25: 1(-2.54,0)
  round 2 hole 1.25: 2(2.54,0)
  silkscreen extent -5.6,-4 5.12,5, body extent -5.78,-4 5.08,5, height 13
REE0036A-MFG [mm]
  rrect50% 0.6x0.2 smd paste+0 mask+0: 1(-1.9,1.8) 2(-1.9,1.4) 3(-1.9,1) 4(-1.9,0.6) 5(-1.9,0.2) 6(-1.9,-0.2) 7(-1.9,-0.6) 8(-1.9,-1) 9(-1.9,-1.4) 10(-1.9,-1.8) 19(1.9,-1.8) 20(1.9,-1.4) 21(1.9,-1) 22(1.9,-0.6) 23(1.9,-0.2) 24(1.9,0.2) 25(1.9,0.6) 26(1.9,1) 27(1.9,1.4) 28(1.9,1.8)
  rrect50% 0.2x0.6 smd paste+0 mask+0: 11(-1.4,-2.4) 12(-1,-2.4) 13(-0.6,-2.4) 14(-0.2,-2.4) 15(0.2,-2.4) 16(0.6,-2.4) 17(1,-2.4) 18(1.4,-2.4) 29(1.4,2.4) 30(1,2.4) 31(0.6,2.4) 32(0.2,2.4) 33(-0.2,2.4) 34(-0.6,2.4) 35(-1,2.4) 36(-1.4,2.4)
  rrect7% 2.7x3.7 smd paste-1000 mask+0: 37(0,0)
  silkscreen extent -2.87,-2.55 2.05,2.55, body extent -2,-2.5 2,2.5, height 0.8
SMA [mm] "Molded Diode, 2-Leads, Body 4.3x2.6mm, IPC Medium Density, based on OnSemi component dimensions and land pattern"
  rect 2x2 smd: 1(-2,0) 2(2,0)
  silkscreen extent -3.66,-1.57 2.79,1.57, body extent -2.6,-1.3 2.6,1.3, height 2.42
SNT-100-BK-G [mil] "Samtec STEP model"
  round 1 on Mech3: 0(0,0)
  body extent -100,-50 100,50, height 344
SOT-23L [mm] "SOT23, 3-Leads, Body 2.9x1.3mm, Pitch 0.95mm, Lead Span 2.5mm, IPC High Density"
  rrect50% 0.8x0.6 smd: 1(-1.1,0.95) 2(-1.1,-0.95) 3(1.1,0)
  silkscreen extent -1.5,-1.5 0.7,1.5, body extent -1.16,-1.45 1.21,1.45, height 1
Testpoint_Keystone_Miniature [mil] "Miniature SMT test point"
  rect 135x70 smd: 1(0,0)
  silkscreen extent -78,-46 78,45, body extent -52,-20 52,20, height 61
TRANS_AOS_DFN3X3 [mm] "Alpha & Omega Semi."
  rect 0.5x0.35 smd mask+0.07: 1(-1.4,0.975) 2(-1.4,0.325) 3(-1.4,-0.325) 4(-1.4,-0.975)
  rect 0.5x0.4 smd mask+0.07: 5(1.4,-0.975) 6(1.4,-0.325) 7(1.4,0.325) 8(1.4,0.975)
  Top Layer region: -0.215,1.13 0.215,1.13 0.215,1.605 -0.215,1.605
  Top Layer region: -0.215,-1.605 0.215,-1.605 0.215,-1.13 -0.215,-1.13
  Top Layer region: -0.63,-1.225 1.35,-1.225 1.35,1.225 -0.63,1.225
  silkscreen extent -2.27,-1.7 1.7,1.7, body extent -1.55,-1.55 1.55,1.55, height 0.9
TSW-102-07-G-S [mm] "Samtec 100mil, 1x2, 230 mil above insulator"
  rrect50% 1.65x1.65 hole 1.016: 1(-1.27,0)
  round 1.65 hole 1.016: 2(1.27,0)
  silkscreen extent -3.17,-1.27 2.54,1.27, body extent -2.54,-1.27 2.54,1.27, height 8.38
WEEE_Minimum [mil] "WEEElie bin"
  silkscreen extent -95,-172 99,104

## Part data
C1 C2 C3 C4 C5 C6 C15 C16 C17 C18 C19 C25 C26 C27 C28 C29 C30 C31 C57 C58 C59 C60: library part CMP-0085894-1, "CAP, CERM, 10 µF, 50 V,+/- 10%, JB, 0805", Cap_Case=0805, Manufacturer=muRata, PartNumber=GRM21BR61H106KE43L, TempCo=JB, Tolerance_%=10%, Value2=50V, ValueDisplayed=10µF
C7 C8 C24 C33: library part CMP-0007011-5, "CAP, CERM, 1 uF, 50 V, +/- 10%, X5R, 0603", Cap_Case=0603, Manufacturer=TDK, Supplier Part Number 1=445-7468-1-ND, TempCo=X5R, Tolerance_%=10%, Value1="0.005522 ohm", Value2=50V, ValueDisplayed=1uF
C9 C10 C20: library part CMP-0006850-4, "CAP, CERM, 0.01 uF, 50 V, +/- 5%, X7R, 0603", Cap_Case=0603, Manufacturer=Kemet, Supplier Part Number 1=399-1092-1-ND, TempCo=X7R, Tolerance_%=5%, Value1=Unknown, Value2=50V, ValueDisplayed=0.01uF
C11 C12: library part CMP-0861060-1, "CAP, CERM, 1000 pF, 50 V,+/- 5%, X7R, 0402", Cap_Case=0402, Manufacturer=AVX, TempCo=X7R, Tolerance_%=5%, Value2=50V, ValueDisplayed=1000pF
C13 C14: library part CMP-0008822-2, "CAP, CERM, 10 uF, 35 V, +/- 10%, X7R, 1206_190", Cap_Case=1206, Manufacturer="Taiyo Yuden", Supplier Part Number 1=587-3007-1-ND, TempCo=X7R, Tolerance_%=10%, Value1=Unknown, Value2=35V, ValueDisplayed=10uF
C21 C22 C23 C61: library part CMP-0012653-3, "CAP, Tantalum Polymer, 33 uF, 50 V, +/- 20%, 0.05 ohm, 7343-43 SMD", Cap_Case=7.3x4.3x4.3mm, Manufacturer=Kemet, Supplier Part Number 1=01AC5423, Tolerance_%=20%, Value1="0.05 ohm", Value2=50V, ValueDisplayed=33uF
C32: library part CMP-0007355-7, "CAP, CERM, 10 uF, 35 V, +/- 20%, X5R, 0603", Cap_Case=0603, Manufacturer=Murata, TempCo=X5R, Tolerance_%=20%, Value1=Unknown, Value2=35V, ValueDisplayed=10uF
C34: library part CMP-0006675-2, "CAP, CERM, 0.1 uF, 50 V, +/- 20%, X7R, 0402", Cap_Case=0402, Manufacturer=MuRata, Supplier Part Number 1=490-10701-1-ND, TempCo=X7R, Tolerance_%=20%, Value1=Unknown, Value2=50V, ValueDisplayed=0.1uF
C35 C38: library part CMP-0006684-2, "CAP, CERM, 0.022 uF, 50 V, +/- 10%, X7R, 0402", Cap_Case=0402, Manufacturer=MuRata, Supplier Part Number 1=490-3884-1-ND, TempCo=X7R, Tolerance_%=10%, Value1=Unknown, Value2=50V, ValueDisplayed=0.022uF
C36 C49 C52: library part CMP-0007449-4, "CAP, CERM, 330 pF, 50 V, +/- 10%, X7R, 0603", Cap_Case=0603, Manufacturer=MuRata, PartNumber=GRM188R71H331KA01D, Supplier Part Number 1=490-1486-1-ND, TempCo=X7R, Tolerance_%=10%, Value1=Unknown, Value2=50V, ValueDisplayed=330pF
C37: library part CMP-0006331-2, "CAP, CERM, 0.068 uF, 50 V, +/- 10%, X7R, AEC-Q200 Grade 1, 0402", Cap_Case=0402, Manufacturer=TDK, Supplier Part Number 1=445-6898-1-ND, TempCo=X7R, Tolerance_%=10%, Value1="0.05606 ohm", Value2=50V, ValueDisplayed=0.068uF
C39 C44 C48: library part CMP-0080610-1, "CAP, CERM, 0.1 µF, 25 V,+/- 10%, X7R, AEC-Q200 Grade 1, 0402", Cap_Case=0402, Manufacturer=TDK, Supplier Part Number 1=445-6902-1-ND, TempCo=X7R, Tolerance_%=10%, Value2=25V, ValueDisplayed=0.1µF
C40 C41 C43 C45: library part CMP-0006410-2, "CAP, CERM, 100 pF, 50 V, +/- 5%, C0G/NP0, 0402", Cap_Case=0402, Manufacturer=MuRata, Supplier Part Number 1=81-GRM1555C1H101JA1D, TempCo=C0G/NP0, Tolerance_%=5%, Value1=Unknown, Value2=50V, ValueDisplayed=100pF
C42 C51: library part CMP-0081010-1, "CAP, CERM, 2.2 µF, 25 V,+/- 20%, X5R, 0402", Cap_Case=0402, Manufacturer=MuRata, Supplier Part Number 1=490-10457-1-ND, TempCo=X5R, Tolerance_%=20%, Value2=25V, ValueDisplayed=2.2µF
C46 C47: library part CMP-0064946-2, "CAP, CERM, 0.1 uF, 50 V,+/- 10%, X7R, 0402", Cap_Case=0402, Manufacturer=TDK, Supplier Part Number 1=445-173610-1-ND, TempCo=X7R, Tolerance_%=10%, Value1=Unknown, Value2=50V, ValueDisplayed=0.1uF
C50: library part CMP-0064928-2, "CAP, CERM, 0.47 uF, 25 V,+/- 10%, X5R, 0402", Cap_Case=0402, Manufacturer=MuRata, Supplier Part Number 1=490-14365-1-ND, TempCo=X5R, Tolerance_%=10%, Value1=Unknown, Value2=25V, ValueDisplayed=0.47uF
C53 C54 C55 C56: library part CMP-0006329-2, "CAP, CERM, 0.033 uF, 50 V, +/- 10%, X7R, AEC-Q200 Grade 1, 0402", Cap_Case=0402, Manufacturer=TDK, Supplier Part Number 1=445-6896-1-ND, TempCo=X7R, Tolerance_%=10%, Value1="0.098477 ohm", Value2=50V, ValueDisplayed=0.033uF
C62: library part CMP-0086249-1, "CAP, CERM, 1 µF, 50 V,+/- 10%, X7R, AEC-Q200 Grade 1, 0805", Cap_Case=0805, Manufacturer=MuRata, TempCo=X7R, Tolerance_%=10%, Value2=50V, ValueDisplayed=1µF
D1: library part CMP-0002827-3, "LED, Green, SMD", Color=green, Manufacturer=Lite-On, PartNumber=LTST-C190GKT, Power_TotalModule=100mW, Value1=0.1W, Value2=2.1V
D2: library part CMP-0028403-2, "Diode, Schottky, 40 V, 2 A, SMA", Manufacturer="Diodes Inc.", Value1=2A, Value2=0.5V
D3: library part CMP-0077061-2, "Diode, Switching, 70 V, 0.25 A, AEC-Q101, SOT-23", Manufacturer=Vishay-Semiconductor, Value1=0.25A, Value2=1.25V
FID1 FID2 FID3 FID4 FID5 FID6: library part CMP-0077181-1, "Fiducial mark.  There is nothing to buy or mount.", Manufacturer=N/A
H1 H2 H3 H4: library part CMP-0003620-1, "Bumpon, Hemisphere, 0.44 X 0.20, Clear", Manufacturer=3M, PartNumber="SJ-5303 (CLEAR)", Supplier Part Number 1=SJ5303-7-ND
J1: library part CMP-0074910-1, "Terminal Block, 5.08 mm, 2x1, Brass, TH", Color=Blue, Current_A=15A, Manufacturer="On-Shore Technology", PartNumber=ED120/2DS, Supplier Part Number 1=ED1609-ND, Voltage_V=300V
J2: library part CMP-0089047-2, "Connector Header Through Hole, Right Angle 4 position 0.100\" (2.54mm)", Current_A=4A, Manufacturer=Molex, Voltage_V=500V
J3 J4: library part CMP-0074910-1, "Terminal Block, 5.08 mm, 2x1, Brass, TH", Color=Blue, Current_A=15A, Manufacturer="On-Shore Technology", Supplier Part Number 1=ED1609-ND, Voltage_V=300V
JP1 JP2: library part CMP-0075405-3, "Header, 100mil, 2x1, Gold, TH", Color=Black, Current_A=6.3A, Manufacturer=Samtec, Supplier Part Number 1=SAM1029-02-ND, Voltage_V=550V
L1_A L1_B: library part CMP-0097234-1, "2.2 µH Shielded Inductor 5.2 A 35mOhm Max", Digikey Part Number=CMLB051H-2R2MS-ND, Manufacturer=Cyntec, Operating Temperature Range="-55°C to +125°C", Test Frequency=100kHz, Tolerance_%=20%
LBL1: library part CMP-0003625-1, "Thermal Transfer Printable Labels, 0.650\" W x 0.200\" H - 10,000 per roll", Manufacturer=Brady, Supplier Part Number 1=97C5133
LOGO2: library part CMP-0074837-2, "IEC 61010-1 Hot Surface Warning", Manufacturer="Texas Instruments"
LOGO3: library part CMP-0074844-1
Logo4: library part CMP-0074769-1
Logo5: library part CMP-0074847-1, "FCC_disclaimer"
Q1A Q1B Q2: library part CMP-0121471-1, "Mosfet Array 30V 50A (Tc) 3.4W (Ta), 33W (Tc), 3.1W (Ta), 30W (Tc) Surface Mount 8-DFN-EP (3.3x3.3)", Digikey Part Number=785-AONP36336TR-ND, Drain To Source Breakdown Voltage=30V, Manufacturer="Alpha & Omega Semiconductor", Operating Temperature Range="-55°C to +150°C", Power_W=3.4/3.1W, Pulse Drain Current=110/88A, Typ Forward Diode Voltage=0.7V
Q3: library part CMP-0000289-1, "MOSFET, N-CH, 30 V, 30 A, FET, 3x0.8x3mm", Alternate Manufacturer=None, Manufacturer=AOS, Supplier Part Number 1=785-1604-1-ND, Value1=0.008, Value2="15.5 nC"
Q5: library part CMP-0000772-1, "MOSFET, N-CH, 60 V, 0.26 A, SOT-23", Alternate Manufacturer=None, Manufacturer="ON Semiconductor", PartNumber=2N7002ET1G, Supplier Part Number 1=2N7002ET1GOSCT-ND, Value2="0.81 nC"
R1: library part CMP-0022268-4, "RES, 2.00 k, 1%, 0.1 W, AEC-Q200 Grade 0, 0603", Manufacturer=Vishay-Dale, PartNumber=CRCW06032K00FKEA, Power_W=100mW, Supplier Part Number 1=541-2.00KHCT-ND, TempCo="100 ppm/C", Tolerance_%=1%, Value2=0.1W, Value_Code=2k00, ValueDisplayed=2.00k
R2: library part CMP-0017299-3, "RES, 10.0, 1%, 0.25 W, AEC-Q200 Grade 0, 1206", Manufacturer=Panasonic, Power_W=250mW, Supplier Part Number 1=P10.0FCT-ND, TempCo="100 ppm/C", Tolerance_%=1%, Value2=0.25W, Value_Code=10R0, ValueDisplayed=10.0
R3 R4 R11 R17 R26 R27: library part CMP-0025958-3, "RES, 10.0 k, 1%, 0.063 W, AEC-Q200 Grade 0, 0402", Manufacturer=Vishay-Dale, Power_W=63mW, Supplier Part Number 1=541-10.0KLCT-ND, TempCo="100 ppm/C", Tolerance_%=1%, Value2=0.063W, Value_Code=10k0, ValueDisplayed=10.0k
R5 R15: library part CMP-0026279-2, "RES, 300 k, 1%, 0.063 W, AEC-Q200 Grade 0, 0402", Manufacturer=Vishay-Dale, Power_W=63mW, Supplier Part Number 1=541-300KLCT-ND, TempCo="100 ppm/C", Tolerance_%=1%, Value2=0.063W, Value_Code=300k
R6: library part CMP-0026721-1, "RES, 100 k, 1%, 0.0625 W, 0402", Manufacturer="Yageo America", Power_W=62.5mW, Supplier Part Number 1=311-100KLRCT-ND, TempCo="100 ppm/C", Tolerance_%=1%, Value2=0.0625W, Value_Code=100k
R7: library part CMP-0078584-1, "RES, 33.0 k, 1%, 0.063 W, 0402", Manufacturer="Yageo America", Power_W=63mW, Supplier Part Number 1=311-33.0KLRCT-ND, TempCo="100 ppm/C", Tolerance_%=1%, Value2=0.063W, Value_Code=33k0, ValueDisplayed=33.0k
R8 R9: library part CMP-0026827-3, "RES, 10, 5%, 0.063 W, AEC-Q200 Grade 0, 0402", Manufacturer=Vishay-Dale, Power_W=63mW, Supplier Part Number 1=541-10JCT-ND, TempCo="200 ppm/C", Tolerance_%=5%, Value2=0.063W, Value_Code=10R0, ValueDisplayed=10
R10: library part CMP-0026893-2, "RES, 2.0 M, 5%, 0.063 W, AEC-Q200 Grade 0, 0402", Manufacturer=Vishay-Dale, Power_W=63mW, Supplier Part Number 1=541-2.0MJCT-ND, TempCo="200 ppm/C", Tolerance_%=5%, Value2=0.063W, Value_Code=2M00, ValueDisplayed=2.0M
R12: library part CMP-0026027-3, "RES, 15.0 k, 1%, 0.063 W, AEC-Q200 Grade 0, 0402", Manufacturer=Vishay-Dale, Power_W=63mW, Supplier Part Number 1=541-15.0KLCT-ND, TempCo="100 ppm/C", Tolerance_%=1%, Value2=0.063W, Value_Code=15k0, ValueDisplayed=15.0k
R13 R18 R19: library part CMP-0025829-4, "RES, 56, 5%, 0.1 W, AEC-Q200 Grade 0, 0603", Manufacturer=Vishay-Dale, PartNumber=CRCW060356R0JNEA, Power_W=100mW, Supplier Part Number 1=541-56GCT-ND, TempCo="200 ppm/C", Tolerance_%=5%, Value2=0.1W, Value_Code=56R0, ValueDisplayed=56
R14: library part CMP-0026336-2, "RES, 3.57 k, 1%, 0.063 W, AEC-Q200 Grade 0, 0402", Manufacturer=Vishay-Dale, Power_W=63mW, Supplier Part Number 1=541-3.57KLCT-ND, TempCo="100 ppm/C", Tolerance_%=1%, Value2=0.063W, Value_Code=3k57, ValueDisplayed=3.57k
R16: library part CMP-0026158-2, "RES, 200 k, 1%, 0.063 W, AEC-Q200 Grade 0, 0402", Manufacturer=Vishay-Dale, Power_W=63mW, Supplier Part Number 1=541-200KLCT-ND, TempCo="100 ppm/C", Tolerance_%=1%, Value2=0.063W, Value_Code=200k
R20: library part CMP-0025743-4, "RES, 1.0, 5%, 0.1 W, AEC-Q200 Grade 0, 0603", Manufacturer=Vishay-Dale, Power_W=100mW, Supplier Part Number 1=541-1.0GCT-ND, TempCo="200 ppm/C", Tolerance_%=5%, Value2=0.1W, Value_Code=1R00, ValueDisplayed=1.0
R21 R22 R23 R24: library part CMP-0026434-2, "RES, 4.99, 1%, 0.063 W, AEC-Q200 Grade 0, 0402", Manufacturer=Vishay-Dale, PartNumber=CRCW04024R99FKED, Power_W=63mW, Supplier Part Number 1=541-4.99LLCT-ND, TempCo="100 ppm/C", Tolerance_%=1%, Value2=0.063W, Value_Code=4R99, ValueDisplayed=4.99
R25: library part CMP-0026824-3, "RES, 100, 5%, 0.063 W, AEC-Q200 Grade 0, 0402", Manufacturer=Vishay-Dale, Power_W=63mW, Supplier Part Number 1=541-100JCT-ND, TempCo="200 ppm/C", Tolerance_%=5%, Value2=0.063W, Value_Code=100R, ValueDisplayed=100
R28: library part CMP-0025958-3, "RES, 10.0 k, 1%, 0.063 W, AEC-Q200 Grade 0, 0402", Manufacturer=Vishay-Dale, PartNumber=CRCW040210K0FKED, Power_W=63mW, Supplier Part Number 1=541-10.0KLCT-ND, TempCo="100 ppm/C", Tolerance_%=1%, Value2=0.063W, Value_Code=10k0, ValueDisplayed=10.0k
R29 R30: library part CMP-0018679-3, "RES, 3.9, 5%, 0.25 W, AEC-Q200 Grade 0, 1206", Manufacturer=Vishay-Dale, PartNumber=CRCW12063R90JNEA, Power_W=250mW, Supplier Part Number 1=541-3.9ECT-ND, TempCo="200 ppm/C", Tolerance_%=5%, Value2=0.25W, Value_Code=3R90
RAC_A RAC_B: library part CMP-0018570-2, "RES, 0.01, 1%, 1 W, 1206", Manufacturer=Vishay-Dale, Power_W=1W, Supplier Part Number 1=WSLP-.01CT-ND, TempCo="75 ppm/C", Tolerance_%=1%, Value_Code=R010, ValueDisplayed=0.01
RSR: library part CMP-0016512-2, "RES, 0.005, 1%, 1.5 W, 2010", Manufacturer="Stackpole Electronics Inc", Power_W=1.5W, Supplier Part Number 1=CSNL2010FT5L00CT-ND, TempCo="50 ppm/C", Tolerance_%=1%, Value_Code=5L000, ValueDisplayed=0.005
SH-JP1 SH-JP2: library part CMP-0003623-3, "Shunt, 100mil, Gold plated, Black", Alternate Manufacturer=3M, Alternate PartNumber=969102-0000-DA, Manufacturer=Samtec, Supplier Part Number 1=SAM8858-ND
TP1 TP8 TP10: library part CMP-0055147-2, "Test Point, Multipurpose, Red, TH", Color=Red, Manufacturer="Keystone Electronics", Supplier Part Number 1=36-5010-ND
TP2 TP9: library part CMP-0055148-2, "Test Point, Multipurpose, Black, TH", Color=Black, Manufacturer="Keystone Electronics", Supplier Part Number 1=36-5011-ND
TP3 TP4 TP5: library part CMP-0055149-2, "Test Point, Multipurpose, White, TH", Color=White, Manufacturer="Keystone Electronics", Supplier Part Number 1=36-5012-ND
TP7: library part CMP-0055152-2, "Test Point, Miniature, SMT", Manufacturer="Keystone Electronics", Supplier Part Number 1=36-5015TR-ND
U1: library part CMP-0094622-2, "SMBus 2- to 5-Cell Narrow VDC Dual Phase Buck-Boost Battery Charge Controller With System Power Monitor and Processor Hot Monitor", Manufacturer="Texas Instruments", Max Supply Voltage=40V, Min Supply Voltage=3.5V, Operating Temperature Range="-40°C to +125°C"
U2: library part CMP-0071020-1, "100 mA, Quasi Low-Dropout Linear Voltage Regulator, 3-pin SOT-23, Pb-Free", Manufacturer="Texas Instruments", PackageTopMarking=L0A*XTT, PowerWise=N
ZZ1: library part CMP-0003616-3
ZZ2: library part CMP-0077236-1, Alternate Manufacturer=-
ZZ3: library part CMP-0077237-1, Alternate Manufacturer=-
ZZ4: library part CMP-0077238-1, Alternate Manufacturer=-

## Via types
v1: diameter 22, hole 10, Top Layer to Bottom Layer, tented both sides, 560 vias
v2: diameter 19.68, hole 7.87, Top Layer to Bottom Layer, tented both sides, 22 vias

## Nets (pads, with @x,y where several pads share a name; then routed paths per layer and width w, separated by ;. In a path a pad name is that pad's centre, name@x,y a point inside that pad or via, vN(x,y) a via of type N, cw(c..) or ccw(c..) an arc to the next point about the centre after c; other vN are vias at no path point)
3V3: C32.2 R1.2 R3.2 R11.1 R17.2 R25.1 R26.2 R27.2 R28.1 TP7.1 U2.1 | length 498.6
  Top Layer w15: R1.2@-1120,-375 v1(-1075,-375)
  Top Layer w25: TP7.1@325,-600 410,-600 v1(435,-625)
  Bottom Layer w15: R28.1@-1130,-325 -1100,-325 -1076.34,-348.66 -1076.34,-373.66 v1(-1075,-375) ; R27.2@-600,-655 v1(-600,-625) ; R26.2@-500,-655 v1(-500,-625) ; R25.1@-400,-655 v1(-400,-625) ; R17.2@-200,-460 v1(-200,-425) ; R11.1@155,215 159.5,215 198.6,175.9 v1@222.84,175.9 ; v1(225,175) 225,174.37 235.5,163.87 235.5,150 R3.2@240,150
ACN_A: C46.2 C56.1 R24.1 U1.9 | length 438
  Bottom Layer w8: C56.1@-385,230 -345.5,230 -342,226.5 -342,132 -299,89 -189.3,89 -178.8,78.5 -163.5,78.5 C46.2@-160,75 -124.8,75 -104.92,55.12 U1.9@-74.8,55.12
ACN_B: C47.2 C55.1 R22.1 U1.7 | length 308.2
  Bottom Layer w8: C55.1@-260,-130 -260,-85.5 -242.5,-68 -242.5,-12.5 -221.5,8.5 -219.94,8.5 -217.44,11 -161,11 C47.2@-160,10 -155.5,10 -141.88,23.62 U1.7@-74.8,23.62
ACP_A: C46.1 C53.1 R23.1 U1.10 | length 424.2
  Bottom Layer w8: C53.1@-265,230 -295.13,230 -301.5,230 -325,206.5 -325,140 -300,115 -289,104 -191,104 -180,115 -140,115 -95.87,70.87 U1.10@-74.8,70.87
ACP_B: C47.1 C54.1 R21.1 U1.8 | length 254.3
  Bottom Layer w8: R21.1@-260,-50 -260,-45.13 -260,-26.7 C54.1@-260,-15 -256.5,-11.5 -256.5,-6.7 -210.8,39 -191.3,39 -180.3,50 -131.82,50 -121.19,39.37 U1.8@-74.8,39.37
BATDRV: Q3.4 U1.26 | length 346.1
  Top Layer w15: Q3.4@338.39,19.88 Q3.4@338.39,19.88 364.94,19.94 v1(365,20)
  Signal Layer 3 w15: v2(115,-45) 180,20 v1(365,20)
  Bottom Layer w8: U1.26@74.8,-39.37 105.58,-39.37 111.21,-45 v2(115,-45)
